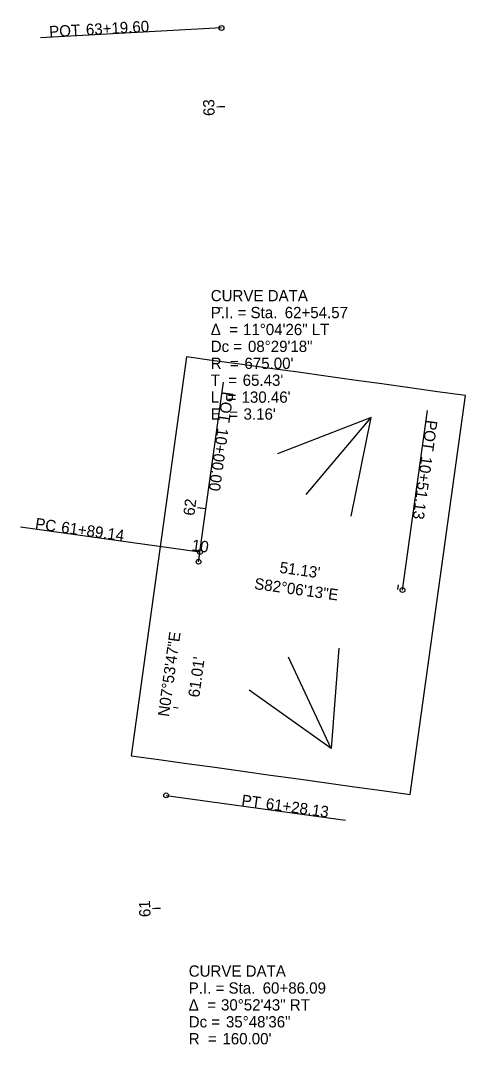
# Model space of a CAD drawing. Extents: x 1564698 to 1565044, y 636021 to 637179.
# Drawn here: x 1564721.1 to 1564831.6, y 636607.6 to 636861.9 of the extents above; entities that cross this region are included whole.
import ezdxf

# ---------------------------------------------------------------- set-up
doc = ezdxf.new("R2010")
doc.units = 0
for name, color, linetype in [('Default', 7, 'Continuous'), ('GE_P_Alignment_1000_Bearings', 7, 'Continuous'), ('GE_P_Alignment_1000_Cardinal_Points', 7, 'Continuous'), ('GE_P_Alignment_1000_Curve_Data', 7, 'Continuous'), ('GE_P_Alignment_1000_Distances', 7, 'Continuous'), ('GE_P_Alignment_1000_Stations', 7, 'Continuous'), ('GE_P_Alignment_100_Bearings', 7, 'Continuous'), ('GE_P_Alignment_100_Cardinal_Points', 7, 'Continuous'), ('GE_P_Alignment_100_Curve_Data', 7, 'Continuous'), ('GE_P_Alignment_100_Distances', 7, 'Continuous'), ('GE_P_Alignment_100_Stations', 7, 'Continuous'), ('GE_P_Alignment_500_Bearings', 7, 'Continuous'), ('GE_P_Alignment_500_Cardinal_Points', 7, 'Continuous'), ('GE_P_Alignment_500_Curve_Data', 7, 'Continuous'), ('GE_P_Alignment_500_Distances', 7, 'Continuous'), ('GE_P_Alignment_500_Stations', 7, 'Continuous'), ('SH_Named_Boundary', 7, 'Continuous')]:
    doc.layers.add(name, color=color, linetype=linetype)

msp = doc.modelspace()

# ---------------------------------------------------------------- linework, layer by layer
at = {"layer": 'Default'}
for p, q in [((1564808.2, 636763.31), (1564784.89, 636754.28)), ((1564792.06, 636744.22), (1564808.2, 636763.31)), ((1564803.18, 636738.82), (1564808.2, 636763.31)), ((1564800.19, 636706.05), (1564798.26, 636681.12)), ((1564798.26, 636681.12), (1564787.67, 636703.77)), ((1564798.26, 636681.12), (1564777.9, 636695.62))]:
    msp.add_line(p, q, dxfattribs=at)
at = {"layer": 'GE_P_Alignment_1000_Cardinal_Points'}
for p, q in [((1564765.32, 636727.5), (1564771.5, 636772.07)), ((1564815.97, 636720.47), (1564822.15, 636765.04))]:
    msp.add_line(p, q, dxfattribs=at)
for centre in [(1564765.32, 636727.5), (1564815.97, 636720.47)]:
    msp.add_circle(centre, 0.6, dxfattribs=at)
at = {"layer": 'GE_P_Alignment_1000_Stations'}
for p, q in [((1564771.02, 636860.06), (1564726.09, 636857.57)), ((1564765.66, 636729.91), (1564721.08, 636736.1)), ((1564765.32, 636727.5), (1564765.6, 636729.48)), ((1564757.28, 636669.48), (1564801.85, 636663.3))]:
    msp.add_line(p, q, dxfattribs=at)
for centre in [(1564771.02, 636860.06), (1564765.66, 636729.91), (1564757.28, 636669.48)]:
    msp.add_circle(centre, 0.6, dxfattribs=at)
at = {"layer": 'GE_P_Alignment_100_Cardinal_Points'}
for p, q in [((1564765.32, 636727.5), (1564771.5, 636772.07)), ((1564815.97, 636720.47), (1564822.15, 636765.04))]:
    msp.add_line(p, q, dxfattribs=at)
for centre in [(1564765.32, 636727.5), (1564815.97, 636720.47)]:
    msp.add_circle(centre, 0.6, dxfattribs=at)
at = {"layer": 'GE_P_Alignment_100_Stations'}
for p, q in [((1564771.02, 636860.06), (1564726.09, 636857.57)), ((1564771.82, 636840.48), (1564769.82, 636840.43)), ((1564771.29, 636790.49), (1564770.09, 636790.55)), ((1564767.06, 636740.68), (1564765.08, 636740.93)), ((1564765.66, 636729.91), (1564721.08, 636736.1)), ((1564765.32, 636727.5), (1564765.6, 636729.48)), ((1564814.85, 636720.63), (1564815.01, 636721.81)), ((1564760.28, 636691.15), (1564759.09, 636691.31)), ((1564757.28, 636669.48), (1564801.85, 636663.3)), ((1564755.87, 636641.43), (1564753.88, 636641.35))]:
    msp.add_line(p, q, dxfattribs=at)
for centre in [(1564771.02, 636860.06), (1564765.66, 636729.91), (1564757.28, 636669.48)]:
    msp.add_circle(centre, 0.6, dxfattribs=at)
at = {"layer": 'GE_P_Alignment_500_Cardinal_Points'}
for p, q in [((1564765.32, 636727.5), (1564771.5, 636772.07)), ((1564815.97, 636720.47), (1564822.15, 636765.04))]:
    msp.add_line(p, q, dxfattribs=at)
for centre in [(1564765.32, 636727.5), (1564815.97, 636720.47)]:
    msp.add_circle(centre, 0.6, dxfattribs=at)
at = {"layer": 'GE_P_Alignment_500_Stations'}
for p, q in [((1564771.02, 636860.06), (1564726.09, 636857.57)), ((1564771.82, 636840.48), (1564770.62, 636840.45)), ((1564767.06, 636740.68), (1564765.87, 636740.83)), ((1564765.66, 636729.91), (1564721.08, 636736.1)), ((1564765.32, 636727.5), (1564765.6, 636729.48)), ((1564757.28, 636669.48), (1564801.85, 636663.3)), ((1564755.87, 636641.43), (1564754.68, 636641.38))]:
    msp.add_line(p, q, dxfattribs=at)
for centre in [(1564771.02, 636860.06), (1564765.66, 636729.91), (1564757.28, 636669.48)]:
    msp.add_circle(centre, 0.6, dxfattribs=at)
at = {"layer": 'SH_Named_Boundary'}
msp.add_lwpolyline([(1564762.29, 636778.39), (1564748.55, 636679.34), (1564755.48, 636678.38), (1564762.42, 636677.42), (1564769.35, 636676.46), (1564776.28, 636675.5), (1564783.22, 636674.53), (1564790.15, 636673.57), (1564797.08, 636672.61), (1564804.02, 636671.65), (1564810.95, 636670.69), (1564817.88, 636669.73), (1564831.62, 636768.78), (1564824.69, 636769.74), (1564817.76, 636770.7), (1564810.82, 636771.66), (1564803.89, 636772.62), (1564796.95, 636773.59), (1564790.02, 636774.55), (1564783.09, 636775.51), (1564776.15, 636776.47), (1564769.22, 636777.43)], close=True, dxfattribs=at)

# ---------------------------------------------------------------- texts
at = {"layer": 'GE_P_Alignment_1000_Bearings'}
msp.add_text('S82°06\'13"E', height=2.8, rotation=352.1036, dxfattribs=at).set_placement((1564779.02, 636720.75))
at = {"layer": 'GE_P_Alignment_1000_Cardinal_Points'}
for s, p in [('POT', (1564771.25, 636769.88)), ('POT', (1564821.9, 636762.83)), ('10+00.00', (1564769.99, 636760.83)), ('10+51.13', (1564820.64, 636753.79))]:
    msp.add_text(s, height=2.8, rotation=262.1036, dxfattribs=at).set_placement(p)
at = {"layer": 'GE_P_Alignment_1000_Curve_Data'}
for s, p in [('CURVE DATA', (1564768.34, 636792.19)), ('P.I. = Sta. ', (1564768.34, 636787.99)), ('62+54.57', (1564786.71, 636787.99)), ('Δ  = ', (1564768.34, 636783.79)), ('11°04\'26" LT', (1564776.36, 636783.79)), ('Dc = ', (1564768.34, 636779.59)), ('08°29\'18"', (1564777.58, 636779.59)), ('R  = ', (1564768.34, 636775.39)), ("675.00'", (1564776.71, 636775.39)), ('T  = ', (1564768.34, 636771.19)), ("65.43'", (1564776.27, 636771.19)), ('L  = ', (1564768.34, 636766.99)), ("130.46'", (1564775.99, 636766.99)), ('E  = ', (1564768.34, 636762.79)), ("3.16'", (1564776.49, 636762.79)), ('CURVE DATA', (1564762.87, 636624.46)), ('P.I. = Sta. ', (1564762.87, 636620.26)), ('60+86.09', (1564781.24, 636620.26)), ('Δ  = ', (1564762.87, 636616.06)), ('30°52\'43" RT', (1564770.89, 636616.06)), ('Dc = ', (1564762.87, 636611.86)), ('35°48\'36"', (1564772.11, 636611.86)), ('R  = ', (1564762.87, 636607.66)), ("160.00'", (1564771.24, 636607.66))]:
    msp.add_text(s, height=2.8, dxfattribs=at).set_placement(p)
for s, p in [('N07°53\'47"E', (1564757.95, 636688.9)), ("61.01'", (1564765.48, 636693.69))]:
    msp.add_text(s, height=2.8, rotation=82.1036, dxfattribs=at).set_placement(p)
at = {"layer": 'GE_P_Alignment_1000_Distances'}
msp.add_text("51.13'", height=2.8, rotation=352.1036, dxfattribs=at).set_placement((1564785.31, 636724.77))
at = {"layer": 'GE_P_Alignment_1000_Stations'}
for s, rotation, p in [('POT', 3.1776, (1564728.29, 636857.74)), ('63+19.60', 3.1776, (1564737.41, 636858.24)), ('PC', 352.1036, (1564724.61, 636735.65)), ('61+89.14', 352.1036, (1564731.07, 636734.76)), ('10', 352.1036, (1564763.5, 636730.32)), ('PT', 352.1036, (1564775.85, 636666.95)), ('61+28.13', 352.1036, (1564781.88, 636666.12))]:
    msp.add_text(s, height=2.8, rotation=rotation, dxfattribs=at).set_placement(p)
at = {"layer": 'GE_P_Alignment_100_Bearings'}
msp.add_text('S82°06\'13"E', height=2.8, rotation=352.1036, dxfattribs=at).set_placement((1564779.02, 636720.75))
at = {"layer": 'GE_P_Alignment_100_Cardinal_Points'}
for s, p in [('POT', (1564771.25, 636769.88)), ('POT', (1564821.9, 636762.83)), ('10+00.00', (1564769.99, 636760.83)), ('10+51.13', (1564820.64, 636753.79))]:
    msp.add_text(s, height=2.8, rotation=262.1036, dxfattribs=at).set_placement(p)
at = {"layer": 'GE_P_Alignment_100_Curve_Data'}
for s, p in [('CURVE DATA', (1564768.34, 636792.19)), ('P.I. = Sta. ', (1564768.34, 636787.99)), ('62+54.57', (1564786.71, 636787.99)), ('Δ  = ', (1564768.34, 636783.79)), ('11°04\'26" LT', (1564776.36, 636783.79)), ('Dc = ', (1564768.34, 636779.59)), ('08°29\'18"', (1564777.58, 636779.59)), ('R  = ', (1564768.34, 636775.39)), ("675.00'", (1564776.71, 636775.39)), ('T  = ', (1564768.34, 636771.19)), ("65.43'", (1564776.27, 636771.19)), ('L  = ', (1564768.34, 636766.99)), ("130.46'", (1564775.99, 636766.99)), ('E  = ', (1564768.34, 636762.79)), ("3.16'", (1564776.49, 636762.79)), ('CURVE DATA', (1564762.87, 636624.46)), ('P.I. = Sta. ', (1564762.87, 636620.26)), ('60+86.09', (1564781.24, 636620.26)), ('Δ  = ', (1564762.87, 636616.06)), ('30°52\'43" RT', (1564770.89, 636616.06)), ('Dc = ', (1564762.87, 636611.86)), ('35°48\'36"', (1564772.11, 636611.86)), ('R  = ', (1564762.87, 636607.66)), ("160.00'", (1564771.24, 636607.66))]:
    msp.add_text(s, height=2.8, dxfattribs=at).set_placement(p)
for s, p in [('N07°53\'47"E', (1564757.95, 636688.9)), ("61.01'", (1564765.48, 636693.69))]:
    msp.add_text(s, height=2.8, rotation=82.1036, dxfattribs=at).set_placement(p)
at = {"layer": 'GE_P_Alignment_100_Distances'}
msp.add_text("51.13'", height=2.8, rotation=352.1036, dxfattribs=at).set_placement((1564785.31, 636724.77))
at = {"layer": 'GE_P_Alignment_100_Stations'}
for s, rotation, p in [('POT', 3.1776, (1564728.29, 636857.74)), ('63+19.60', 3.1776, (1564737.41, 636858.24)), ('63', 91.5139, (1564769.33, 636838.24)), ('62', 83.0256, (1564764.27, 636738.82)), ('PC', 352.1036, (1564724.61, 636735.65)), ('61+89.14', 352.1036, (1564731.07, 636734.76)), ('10', 352.1036, (1564763.5, 636730.32)), ('PT', 352.1036, (1564775.85, 636666.95)), ('61+28.13', 352.1036, (1564781.88, 636666.12)), ('61', 92.1763, (1564753.41, 636639.31))]:
    msp.add_text(s, height=2.8, rotation=rotation, dxfattribs=at).set_placement(p)
at = {"layer": 'GE_P_Alignment_500_Bearings'}
msp.add_text('S82°06\'13"E', height=2.8, rotation=352.1036, dxfattribs=at).set_placement((1564779.02, 636720.75))
at = {"layer": 'GE_P_Alignment_500_Cardinal_Points'}
for s, p in [('POT', (1564771.25, 636769.88)), ('POT', (1564821.9, 636762.83)), ('10+00.00', (1564769.99, 636760.83)), ('10+51.13', (1564820.64, 636753.79))]:
    msp.add_text(s, height=2.8, rotation=262.1036, dxfattribs=at).set_placement(p)
at = {"layer": 'GE_P_Alignment_500_Curve_Data'}
for s, p in [('CURVE DATA', (1564768.34, 636792.19)), ('P.I. = Sta. ', (1564768.34, 636787.99)), ('62+54.57', (1564786.71, 636787.99)), ('Δ  = ', (1564768.34, 636783.79)), ('11°04\'26" LT', (1564776.36, 636783.79)), ('Dc = ', (1564768.34, 636779.59)), ('08°29\'18"', (1564777.58, 636779.59)), ('R  = ', (1564768.34, 636775.39)), ("675.00'", (1564776.71, 636775.39)), ('T  = ', (1564768.34, 636771.19)), ("65.43'", (1564776.27, 636771.19)), ('L  = ', (1564768.34, 636766.99)), ("130.46'", (1564775.99, 636766.99)), ('E  = ', (1564768.34, 636762.79)), ("3.16'", (1564776.49, 636762.79)), ('CURVE DATA', (1564762.87, 636624.46)), ('P.I. = Sta. ', (1564762.87, 636620.26)), ('60+86.09', (1564781.24, 636620.26)), ('Δ  = ', (1564762.87, 636616.06)), ('30°52\'43" RT', (1564770.89, 636616.06)), ('Dc = ', (1564762.87, 636611.86)), ('35°48\'36"', (1564772.11, 636611.86)), ('R  = ', (1564762.87, 636607.66)), ("160.00'", (1564771.24, 636607.66))]:
    msp.add_text(s, height=2.8, dxfattribs=at).set_placement(p)
for s, p in [('N07°53\'47"E', (1564757.95, 636688.9)), ("61.01'", (1564765.48, 636693.69))]:
    msp.add_text(s, height=2.8, rotation=82.1036, dxfattribs=at).set_placement(p)
at = {"layer": 'GE_P_Alignment_500_Distances'}
msp.add_text("51.13'", height=2.8, rotation=352.1036, dxfattribs=at).set_placement((1564785.31, 636724.77))
at = {"layer": 'GE_P_Alignment_500_Stations'}
for s, rotation, p in [('POT', 3.1776, (1564728.29, 636857.74)), ('63+19.60', 3.1776, (1564737.41, 636858.24)), ('PC', 352.1036, (1564724.61, 636735.65)), ('61+89.14', 352.1036, (1564731.07, 636734.76)), ('10', 352.1036, (1564763.5, 636730.32)), ('PT', 352.1036, (1564775.85, 636666.95)), ('61+28.13', 352.1036, (1564781.88, 636666.12))]:
    msp.add_text(s, height=2.8, rotation=rotation, dxfattribs=at).set_placement(p)

doc.saveas('drawing.dxf')
